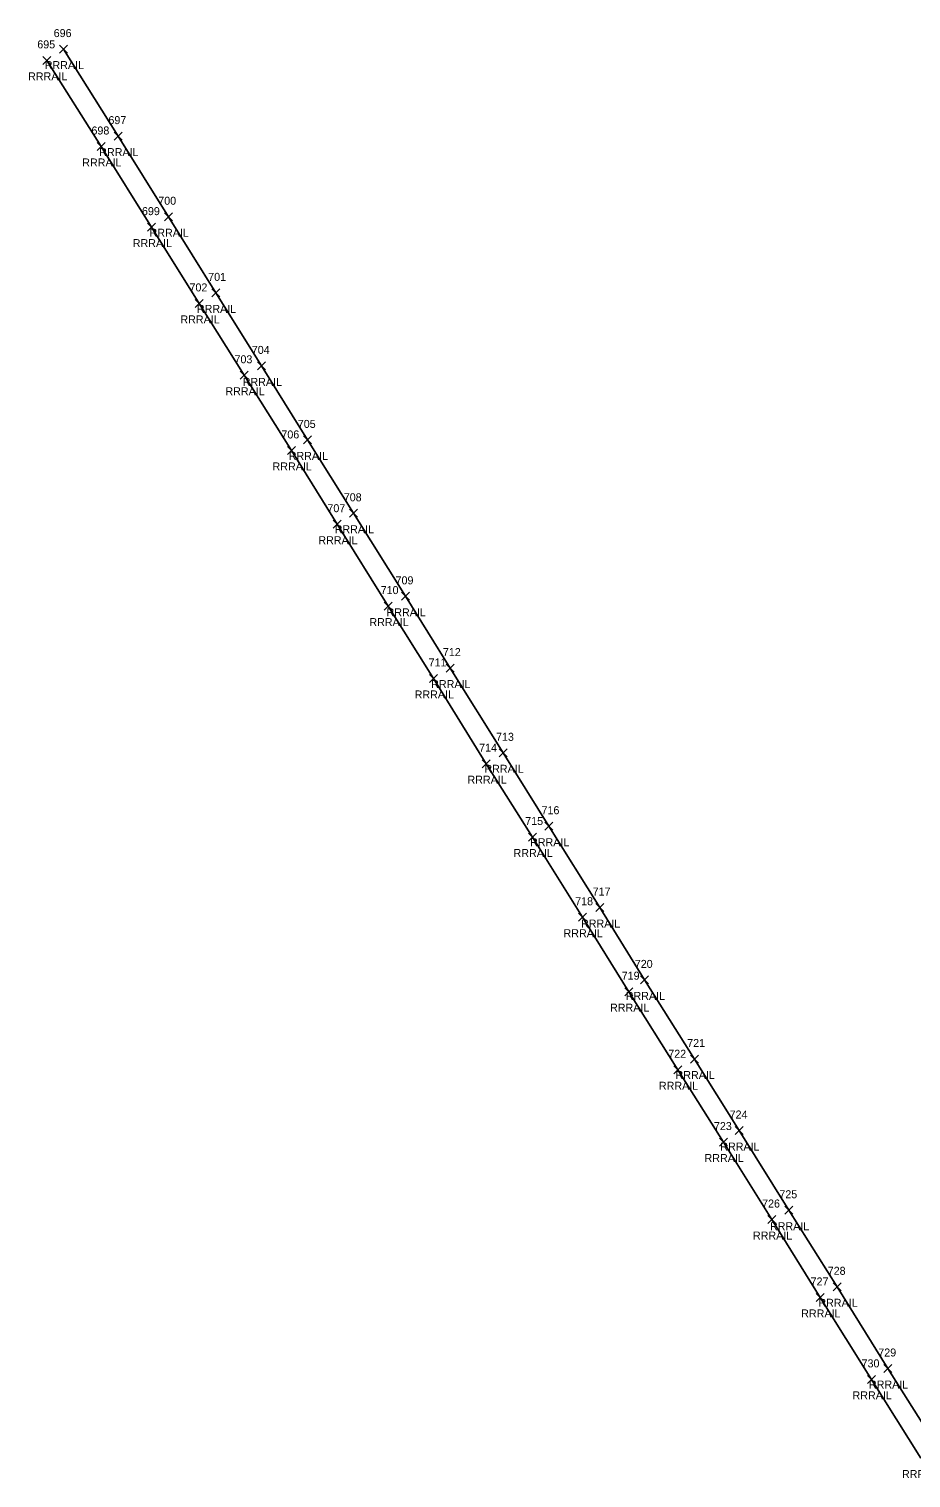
# Model space of a CAD drawing. Extents: x 1679360 to 1685861, y 903420 to 905946.
# Drawn here: x 1679359.6 to 1679580, y 904388.1 to 904750.3 of the extents above; entities that cross this region are included whole.
import ezdxf

# ---------------------------------------------------------------- set-up
doc = ezdxf.new("R2010")
doc.units = 0
for name, color, linetype in [('R_A', 7, 'Continuous'), ('R_I', 7, 'Continuous'), ('R_TIC', 7, 'Continuous'), ('RR', 7, 'Continuous')]:
    doc.layers.add(name, color=color, linetype=linetype)

msp = doc.modelspace()

# ---------------------------------------------------------------- linework, layer by layer
at = {"layer": 'R_TIC'}
for points in [[(1679363.06, 904741.46), (1679365.06, 904743.46)], [(1679365.06, 904741.46), (1679363.06, 904743.46)], [(1679367.21, 904744.28), (1679369.21, 904746.28)], [(1679369.21, 904744.28), (1679367.21, 904746.28)], [(1679376.6, 904719.93), (1679378.6, 904721.93)], [(1679378.6, 904719.93), (1679376.6, 904721.93)], [(1679380.84, 904722.52), (1679382.84, 904724.52)], [(1679382.84, 904722.52), (1679380.84, 904724.52)], [(1679393.42, 904702.37), (1679395.42, 904704.37)], [(1679395.42, 904702.37), (1679393.42, 904704.37)], [(1679389.23, 904699.77), (1679391.23, 904701.77)], [(1679391.23, 904699.77), (1679389.23, 904701.77)], [(1679405.25, 904683.34), (1679407.25, 904685.34)], [(1679407.25, 904683.34), (1679405.25, 904685.34)], [(1679401.13, 904680.7), (1679403.13, 904682.7)], [(1679403.13, 904680.7), (1679401.13, 904682.7)], [(1679416.7, 904665.08), (1679418.7, 904667.08)], [(1679418.7, 904665.08), (1679416.7, 904667.08)], [(1679412.38, 904662.74), (1679414.38, 904664.74)], [(1679414.38, 904662.74), (1679412.38, 904664.74)], [(1679424.16, 904643.95), (1679426.16, 904645.95)], [(1679426.16, 904643.95), (1679424.16, 904645.95)], [(1679428.2, 904646.58), (1679430.2, 904648.58)], [(1679430.2, 904646.58), (1679428.2, 904648.58)], [(1679435.6, 904625.51), (1679437.6, 904627.51)], [(1679437.6, 904625.51), (1679435.6, 904627.51)], [(1679439.69, 904628.24), (1679441.69, 904630.24)], [(1679441.69, 904628.24), (1679439.69, 904630.24)], [(1679452.64, 904607.48), (1679454.64, 904609.48)], [(1679454.64, 904607.48), (1679452.64, 904609.48)], [(1679448.36, 904605.04), (1679450.36, 904607.04)], [(1679450.36, 904605.04), (1679448.36, 904607.04)], [(1679463.81, 904589.54), (1679465.81, 904591.54)], [(1679465.81, 904589.54), (1679463.81, 904591.54)], [(1679459.68, 904586.94), (1679461.68, 904588.94)], [(1679461.68, 904586.94), (1679459.68, 904588.94)], [(1679477.11, 904568.36), (1679479.11, 904570.36)], [(1679479.11, 904568.36), (1679477.11, 904570.36)], [(1679472.88, 904565.64), (1679474.88, 904567.64)], [(1679474.88, 904565.64), (1679472.88, 904567.64)], [(1679488.53, 904550.01), (1679490.53, 904552.01)], [(1679490.53, 904550.01), (1679488.53, 904552.01)], [(1679484.4, 904547.31), (1679486.4, 904549.31)], [(1679486.4, 904547.31), (1679484.4, 904549.31)], [(1679496.89, 904527.26), (1679498.89, 904529.26)], [(1679498.89, 904527.26), (1679496.89, 904529.26)], [(1679501.25, 904529.68), (1679503.25, 904531.68)], [(1679503.25, 904529.68), (1679501.25, 904531.68)], [(1679512.44, 904511.59), (1679514.44, 904513.59)], [(1679514.44, 904511.59), (1679512.44, 904513.59)], [(1679508.52, 904508.65), (1679510.52, 904510.65)], [(1679510.52, 904508.65), (1679508.52, 904510.65)], [(1679524.88, 904491.82), (1679526.88, 904493.82)], [(1679526.88, 904491.82), (1679524.88, 904493.82)], [(1679520.73, 904489.13), (1679522.73, 904491.13)], [(1679522.73, 904489.13), (1679520.73, 904491.13)], [(1679536.06, 904473.94), (1679538.06, 904475.94)], [(1679538.06, 904473.94), (1679536.06, 904475.94)], [(1679532.13, 904471.06), (1679534.13, 904473.06)], [(1679534.13, 904471.06), (1679532.13, 904473.06)], [(1679544.23, 904451.69), (1679546.23, 904453.69)], [(1679546.23, 904451.69), (1679544.23, 904453.69)], [(1679548.48, 904454.01), (1679550.48, 904456.01)], [(1679550.48, 904454.01), (1679548.48, 904456.01)], [(1679560.58, 904434.87), (1679562.58, 904436.87)], [(1679562.58, 904434.87), (1679560.58, 904436.87)], [(1679556.29, 904432.21), (1679558.29, 904434.21)], [(1679558.29, 904432.21), (1679556.29, 904434.21)], [(1679569.12, 904411.73), (1679571.12, 904413.73)], [(1679571.12, 904411.73), (1679569.12, 904413.73)], [(1679573.22, 904414.45), (1679575.22, 904416.45)], [(1679575.22, 904414.45), (1679573.22, 904416.45)]]:
    msp.add_lwpolyline(points, dxfattribs=at)
at = {"layer": 'RR'}
for points in [[(1679368.21, 904745.28), (1679381.84, 904723.52), (1679394.42, 904703.37), (1679406.25, 904684.34), (1679417.7, 904666.08), (1679429.2, 904647.58), (1679440.69, 904629.24), (1679453.64, 904608.48), (1679464.81, 904590.54), (1679478.11, 904569.36), (1679489.53, 904551.01), (1679502.25, 904530.68), (1679513.44, 904512.59), (1679525.88, 904492.82), (1679537.06, 904474.94), (1679549.48, 904455.01), (1679561.58, 904435.87), (1679574.22, 904415.45), (1679586.83, 904395.51)], [(1679364.06, 904742.46), (1679377.6, 904720.93), (1679390.23, 904700.77), (1679402.13, 904681.7), (1679413.38, 904663.74), (1679425.16, 904644.95), (1679436.6, 904626.51), (1679449.36, 904606.04), (1679460.68, 904587.94), (1679473.88, 904566.64), (1679485.4, 904548.31), (1679497.89, 904528.26), (1679509.52, 904509.65), (1679521.73, 904490.13), (1679533.13, 904472.06), (1679545.23, 904452.69), (1679557.29, 904433.21), (1679570.12, 904412.73), (1679582.48, 904393.07)]]:
    msp.add_lwpolyline(points, dxfattribs=at)

# ---------------------------------------------------------------- texts
at = {"layer": 'R_A'}
for p in [(1679359.35, 904737.46), (1679363.51, 904740.28), (1679372.89, 904715.93), (1679377.13, 904718.52), (1679389.71, 904698.37), (1679385.52, 904695.77), (1679401.54, 904679.34), (1679397.42, 904676.7), (1679408.67, 904658.74), (1679412.99, 904661.08), (1679420.45, 904639.95), (1679424.49, 904642.58), (1679431.89, 904621.51), (1679435.98, 904624.24), (1679448.94, 904603.48), (1679444.65, 904601.04), (1679460.1, 904585.54), (1679455.97, 904582.94), (1679473.4, 904564.36), (1679469.17, 904561.64), (1679484.82, 904546.01), (1679480.69, 904543.31), (1679497.54, 904525.68), (1679493.18, 904523.26), (1679508.73, 904507.59), (1679504.81, 904504.65), (1679521.17, 904487.82), (1679517.02, 904485.13), (1679532.35, 904469.94), (1679528.42, 904467.06), (1679540.52, 904447.69), (1679544.77, 904450.01), (1679556.87, 904430.87), (1679552.58, 904428.21), (1679565.41, 904407.73), (1679569.51, 904410.45), (1679577.77, 904388.07)]:
    msp.add_text('RRRAIL', height=2, dxfattribs=at).set_placement(p)
at = {"layer": 'R_I'}
for s, p in [('696', (1679365.75, 904748.28)), ('695', (1679361.65, 904745.46)), ('697', (1679379.43, 904726.52)), ('698', (1679375.19, 904723.93)), ('700', (1679391.89, 904706.37)), ('699', (1679387.81, 904703.77)), ('701', (1679404.37, 904687.34)), ('702', (1679399.69, 904684.7)), ('704', (1679415.26, 904669.08)), ('703', (1679410.94, 904666.74)), ('705', (1679426.76, 904650.58)), ('706', (1679422.66, 904647.95)), ('708', (1679438.25, 904632.24)), ('707', (1679434.16, 904629.51)), ('709', (1679451.2, 904611.48)), ('710', (1679447.48, 904609.04)), ('712', (1679463.02, 904593.54)), ('711', (1679459.45, 904590.94)), ('713', (1679476.31, 904572.36)), ('714', (1679472.08, 904569.64)), ('716', (1679487.68, 904554.01)), ('715', (1679483.6, 904551.31)), ('718', (1679496.09, 904531.26)), ('717', (1679500.45, 904533.68)), ('720', (1679510.99, 904515.59)), ('719', (1679507.72, 904512.65)), ('721', (1679524.09, 904495.82)), ('722', (1679519.36, 904493.13)), ('724', (1679534.69, 904477.94)), ('723', (1679530.77, 904475.06)), ('726', (1679542.81, 904455.69)), ('725', (1679547.12, 904458.01)), ('728', (1679559.21, 904438.87)), ('727', (1679554.93, 904436.21)), ('730', (1679567.67, 904415.73)), ('729', (1679571.85, 904418.45))]:
    msp.add_text(s, height=2, dxfattribs=at).set_placement(p)

doc.saveas('drawing.dxf')
